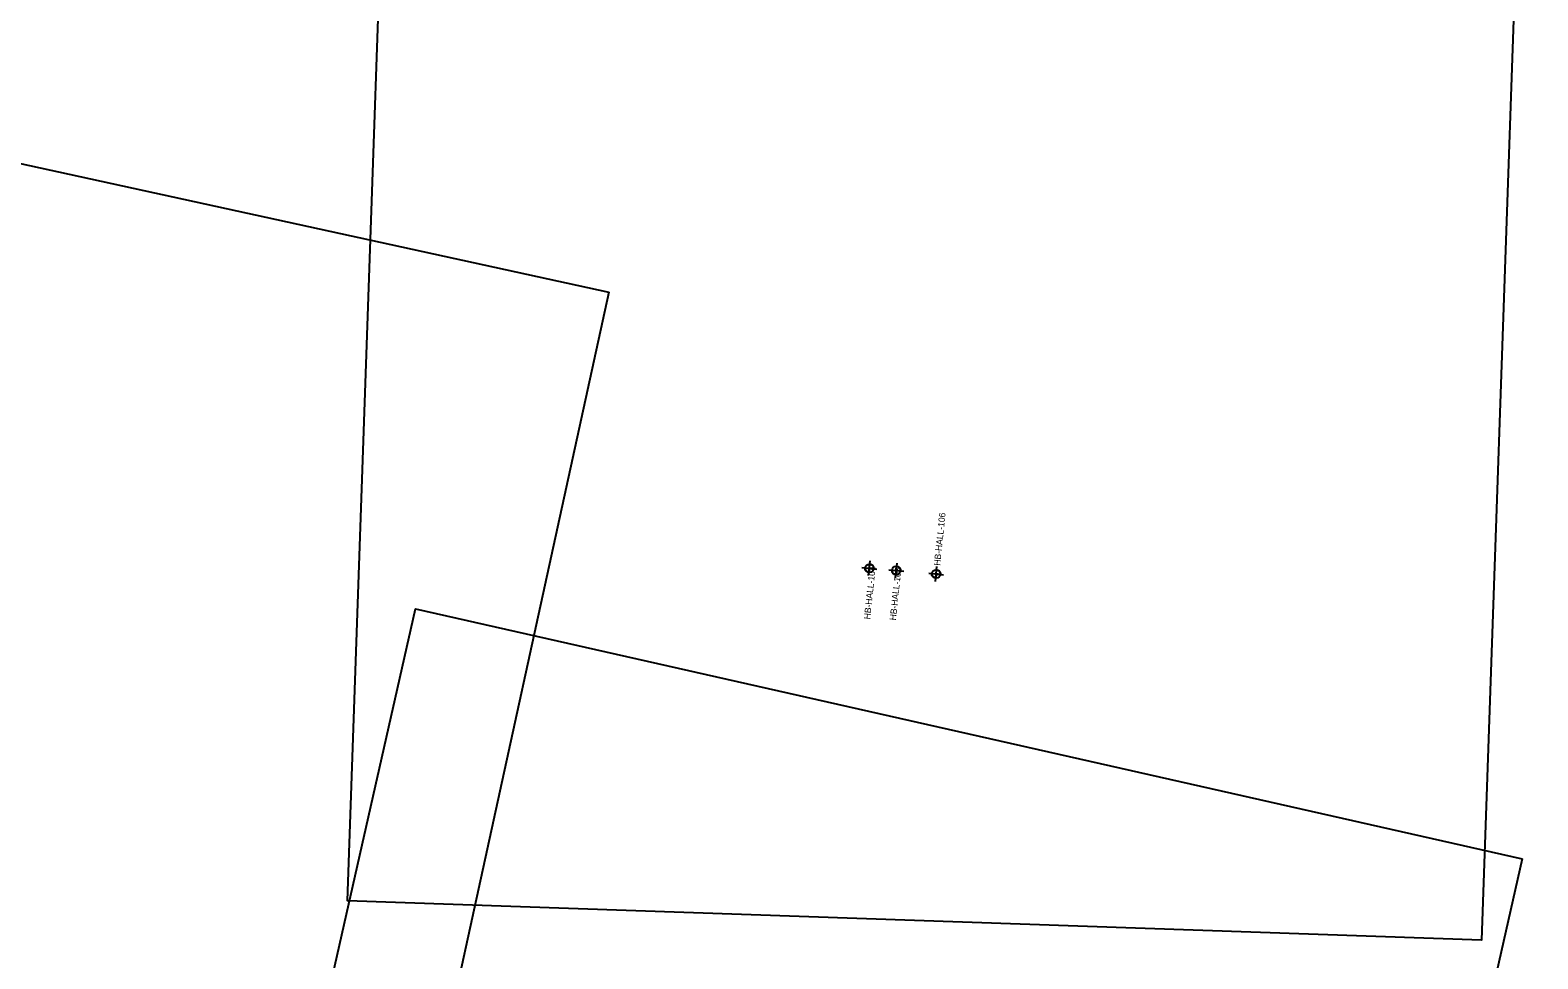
# Model space of a CAD drawing. Extents: x 1136334 to 1137758, y 528745 to 531454.
# Drawn here: x 1137018 to 1137716, y 530052 to 530482 of the extents above; entities that cross this region are included whole.
import ezdxf

# ---------------------------------------------------------------- set-up
doc = ezdxf.new("R2010")
doc.units = 0
doc.layers.add('PLOT BOUNDARY', color=7, linetype='Continuous')
doc.layers.add('ROCKS', color=7, linetype='Continuous')

msp = doc.modelspace()

# ---------------------------------------------------------------- linework, layer by layer
at = {"layer": 'PLOT BOUNDARY'}
for points in [[(1137715.84, 530810.29), (1137689.75, 530060.75), (1137165.06, 530079.02), (1137191.16, 530828.56)], [(1137285.97, 530360.56), (1137125.85, 529627.85), (1136612.96, 529739.94), (1136773.08, 530472.64)], [(1137708.64, 530098.42), (1137543.37, 529366.86), (1137031.27, 529482.55), (1137196.54, 530214.11)]]:
    msp.add_lwpolyline(points, close=True, dxfattribs=at)
at = {"layer": 'ROCKS'}
for p, q in [((1137406.2, 530229.42), (1137406.91, 530236.27)), ((1137418.65, 530228.35), (1137419.36, 530235.2)), ((1137437.09, 530226.77), (1137437.79, 530233.62)), ((1137403.13, 530233.2), (1137409.98, 530232.49)), ((1137415.58, 530232.13), (1137422.43, 530231.42)), ((1137434.02, 530230.55), (1137440.86, 530229.84))]:
    msp.add_line(p, q, dxfattribs=at)
for points in [[(1137406.55, 530232.84), (1137406.76, 530234.8), (1137407.03, 530234.75), (1137407.29, 530234.67), (1137407.54, 530234.54), (1137407.8, 530234.37), (1137407.98, 530234.2), (1137408.2, 530233.91), (1137408.32, 530233.71), (1137408.47, 530233.28), (1137408.52, 530232.93), (1137408.51, 530232.64)], [(1137419.01, 530231.78), (1137419.21, 530233.73), (1137419.48, 530233.68), (1137419.74, 530233.6), (1137419.99, 530233.48), (1137420.25, 530233.3), (1137420.43, 530233.13), (1137420.66, 530232.85), (1137420.77, 530232.65), (1137420.93, 530232.22), (1137420.97, 530231.87), (1137420.97, 530231.57)], [(1137406.55, 530232.84), (1137406.35, 530230.88), (1137406.08, 530230.93), (1137405.82, 530231.02), (1137405.57, 530231.14), (1137405.31, 530231.31), (1137405.13, 530231.48), (1137404.9, 530231.77), (1137404.79, 530231.97), (1137404.63, 530232.4), (1137404.59, 530232.75), (1137404.59, 530233.04)], [(1137419.01, 530231.78), (1137418.8, 530229.82), (1137418.53, 530229.87), (1137418.27, 530229.95), (1137418.02, 530230.07), (1137417.76, 530230.25), (1137417.58, 530230.42), (1137417.35, 530230.7), (1137417.24, 530230.9), (1137417.09, 530231.33), (1137417.04, 530231.68), (1137417.05, 530231.98)], [(1137437.44, 530230.2), (1137437.24, 530228.24), (1137436.97, 530228.29), (1137436.7, 530228.37), (1137436.46, 530228.49), (1137436.2, 530228.67), (1137436.01, 530228.84), (1137435.79, 530229.13), (1137435.67, 530229.33), (1137435.52, 530229.76), (1137435.47, 530230.11), (1137435.48, 530230.4)], [(1137437.44, 530230.2), (1137437.64, 530232.16), (1137437.91, 530232.11), (1137438.18, 530232.02), (1137438.42, 530231.9), (1137438.68, 530231.73), (1137438.87, 530231.55), (1137439.09, 530231.27), (1137439.21, 530231.07), (1137439.36, 530230.64), (1137439.4, 530230.29), (1137439.4, 530229.99)]]:
    msp.add_lwpolyline(points, close=True, dxfattribs=at)
for centre in [(1137406.55, 530232.84), (1137419.01, 530231.78), (1137437.44, 530230.2)]:
    msp.add_circle(centre, 1.97, dxfattribs=at)

# ---------------------------------------------------------------- texts
for s, p in [('HB-HALL-106', (1137439.3, 530233.94)), ('HB-HALL-104', (1137406.94, 530209.1)), ('HB-HALL-105', (1137418.85, 530208.62))]:
    msp.add_text(s, height=2.9528, rotation=84.0839, dxfattribs=at).set_placement(p)

doc.saveas('drawing.dxf')
